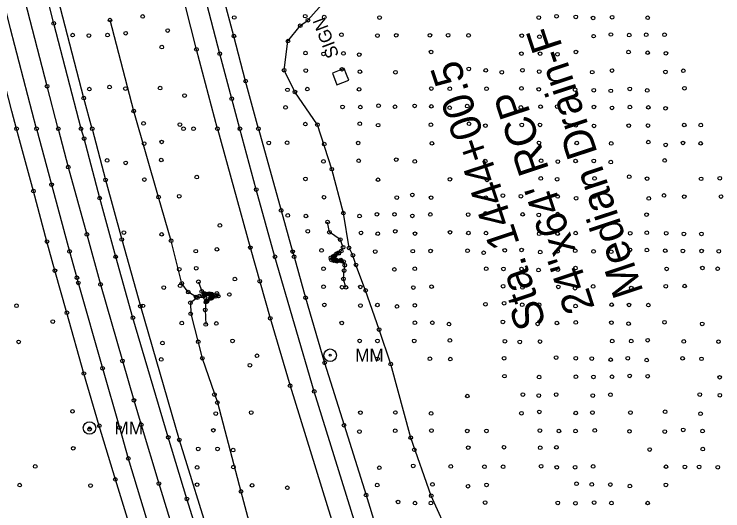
# Model space of a CAD drawing. Extents: x 20503438 to 20508873, y 7964251 to 7984667.
# Drawn here: x 20505603 to 20505990.8, y 7976920.6 to 7977192.3 of the extents above; entities that cross this region are included whole.
import ezdxf

# ---------------------------------------------------------------- set-up
doc = ezdxf.new("R2010")
doc.units = 0
for name, color, linetype in [('SurBreakLine', 7, 'Continuous'), ('SurConcreteSlab', 7, 'Continuous'), ('SurDrainageArrowUp', 7, 'Continuous'), ('SurEdgeRoadPaved', 7, 'Continuous'), ('SurEdgeShoulderPaved', 7, 'Continuous'), ('SurPointsNonDTM', 7, 'Continuous'), ('SurRoadPoints', 7, 'Continuous'), ('SurSurveyPoints', 7, 'Continuous'), ('SurTxtDrainage', 7, 'Continuous')]:
    doc.layers.add(name, color=color, linetype=linetype)

msp = doc.modelspace()

# ---------------------------------------------------------------- linework, layer by layer
at = {"layer": 'SurBreakLine'}
for points in [[(20505627.16, 7977129.6), (20505621, 7977152.86), (20505604.98, 7977215.01)], [(20505714.24, 7977129.6), (20505702.74, 7977172.96), (20505693.54, 7977209.72)], [(20505627.16, 7977129.6), (20505632.6, 7977108.64), (20505642.78, 7977071.79), (20505650.26, 7977044.44), (20505662.27, 7977002.64), (20505668.49, 7976981.08), (20505672.51, 7976967.67), (20505682.17, 7976935.56), (20505689.5, 7976911.63)], [(20505714.24, 7977129.6), (20505732.22, 7977064.58), (20505743.15, 7977025.95), (20505753.96, 7976989.01), (20505776.7, 7976915.92), (20505797.67, 7976849.64), (20505822.91, 7976773.82), (20505835.6, 7976736.75), (20505851.23, 7976692.18), (20505881.78, 7976610.15), (20505895.32, 7976574.73), (20505907.09, 7976544.26), (20505948.4, 7976440.27), (20505966.85, 7976397.06)], [(20505784.52, 7977042.85), (20505783.2, 7977047.48), (20505783.52, 7977052.06), (20505783.93, 7977054.98), (20505783.23, 7977056.95), (20505781.78, 7977057.35), (20505779.53, 7977057.07), (20505777.83, 7977057.46), (20505776.58, 7977057.82), (20505776.33, 7977059.03), (20505777.62, 7977059.8), (20505779.41, 7977061.23), (20505780.72, 7977061.88), (20505781.97, 7977062.67), (20505783.02, 7977064.79), (20505781.42, 7977068.98), (20505775.49, 7977072.98), (20505774.5, 7977078.6)], [(20505703.86, 7977045.89), (20505705.66, 7977040.61), (20505706.75, 7977039.62), (20505707.23, 7977039.41), (20505709.74, 7977039.48), (20505711, 7977039.27), (20505713.91, 7977039.54), (20505714.72, 7977038.09), (20505713.52, 7977038.02), (20505712.02, 7977037.77), (20505710.95, 7977036.83), (20505708.44, 7977035.03), (20505707.88, 7977034.78), (20505707.54, 7977030.55), (20505707.82, 7977022.56)]]:
    msp.add_lwpolyline(points, dxfattribs=at)
at = {"layer": 'SurConcreteSlab'}
for points in [[(20505781.78, 7977057.76), (20505779.2, 7977057.84), (20505778.28, 7977058.25), (20505777.84, 7977058.9), (20505778.13, 7977059.52), (20505780.62, 7977061.42), (20505780.54, 7977061.59), (20505778.63, 7977060.38), (20505777.95, 7977059.64), (20505777.68, 7977058.92), (20505777.91, 7977058.29), (20505778.53, 7977057.75), (20505779.54, 7977057.44), (20505781.82, 7977057.49)], [(20505707.23, 7977039.07), (20505709.48, 7977039.08), (20505710.47, 7977038.91), (20505711.08, 7977038.48), (20505711.05, 7977038), (20505710.84, 7977037.38), (20505710.22, 7977036.7), (20505708.23, 7977035.42), (20505708.39, 7977035.2), (20505710.83, 7977036.95), (20505711.26, 7977037.65), (20505711.23, 7977038.59), (20505710.57, 7977039.1), (20505709.82, 7977039.27), (20505707.52, 7977039.36)]]:
    msp.add_lwpolyline(points, close=True, dxfattribs=at)
at = {"layer": 'SurDrainageArrowUp'}
for points in [[(20505841.57, 7976905.79), (20505831.2, 7976928.87), (20505820.02, 7976960.63), (20505809.08, 7977000.91), (20505802.72, 7977019.77), (20505795.33, 7977041.18), (20505790.04, 7977055.14), (20505788.34, 7977060.44), (20505786.23, 7977064.44), (20505783.14, 7977083.44), (20505776.83, 7977107.5), (20505768.94, 7977131.75), (20505756.6, 7977149.72), (20505750.73, 7977161.63), (20505752.84, 7977177.52), (20505759.52, 7977185.95), (20505763.74, 7977188.93), (20505777.8, 7977204.89)], [(20505707.08, 7977038.35), (20505704.42, 7977038.11), (20505702.5, 7977037.59), (20505698.25, 7977040.29), (20505694.71, 7977045.04), (20505688.86, 7977068.33), (20505681.98, 7977092.2), (20505668.42, 7977139.31), (20505655.45, 7977189.07)], [(20505707.4, 7977037.27), (20505703.17, 7977037.15), (20505699.48, 7977034.43), (20505699.58, 7977028.38), (20505705.95, 7977004.1), (20505714.17, 7976979.83), (20505727.11, 7976931.22), (20505739.64, 7976883.92), (20505750.55, 7976861.92), (20505767.66, 7976808.37), (20505782.7, 7976762.01), (20505813.56, 7976666.44), (20505830.86, 7976618.86), (20505849.64, 7976572.31), (20505867.43, 7976526.9), (20505886.99, 7976479.14), (20505905.22, 7976432.12), (20505914.25, 7976410.54), (20505924.33, 7976390.07)]]:
    msp.add_lwpolyline(points, dxfattribs=at)
at = {"layer": 'SurEdgeRoadPaved'}
for points in [[(20505639.58, 7977129.6), (20505624.63, 7977187.2), (20505615.58, 7977223)], [(20505615.26, 7977129.6), (20505601.04, 7977184.16), (20505592.64, 7977217.57)], [(20505726.55, 7977129.6), (20505722.04, 7977146), (20505715.52, 7977170.61), (20505707.28, 7977202.25)], [(20505667.23, 7976909.32), (20505658.37, 7976937.83), (20505649.59, 7976967.17), (20505641.18, 7976995.74), (20505631.87, 7977028.97), (20505625.28, 7977051.99), (20505620.94, 7977067.88), (20505613.51, 7977095.5), (20505604.33, 7977129.6)], [(20505615.26, 7977129.6), (20505623.45, 7977099.02), (20505633.31, 7977062.48), (20505637.29, 7977048.14), (20505638.09, 7977045.27), (20505651.36, 7976998.65), (20505660.6, 7976966.16), (20505665.45, 7976949.3), (20505675.3, 7976916.84), (20505683.04, 7976892.36), (20505688.19, 7976876.04), (20505701.22, 7976835.1), (20505711.07, 7976804.73), (20505720.51, 7976776.33), (20505734.63, 7976734.41), (20505745.53, 7976702.88), (20505759.33, 7976663.75), (20505771.44, 7976629.94), (20505784.37, 7976595.48), (20505797.7, 7976560.8), (20505811.46, 7976525.6), (20505854.48, 7976420.23), (20505870.79, 7976380.67)], [(20505888.02, 7976400.52), (20505875.61, 7976430.87), (20505858.33, 7976472.87), (20505843.45, 7976509.59), (20505829.21, 7976545.44), (20505815.32, 7976581.21), (20505788.67, 7976653.43), (20505776.13, 7976688.41), (20505761.74, 7976729.52), (20505752.69, 7976755.73), (20505741.62, 7976788.54), (20505730.6, 7976822.27), (20505708.77, 7976891.06), (20505697.53, 7976927.13), (20505687.33, 7976960.85), (20505667.97, 7977026.21), (20505658.55, 7977059.63), (20505649.78, 7977091.67), (20505641.23, 7977124.22), (20505639.58, 7977129.6)], [(20505976.84, 7976403.26), (20505970.11, 7976419.35), (20505955.7, 7976454.64), (20505927.75, 7976523.73), (20505913.86, 7976558.72), (20505899.14, 7976596.95), (20505885.21, 7976633.89), (20505872.02, 7976669.96), (20505859.99, 7976702.29), (20505847.36, 7976737.97), (20505835.6, 7976772.91), (20505824.01, 7976806.63), (20505812.42, 7976841.79), (20505791.67, 7976907.29), (20505767.2, 7976985.93), (20505745.71, 7977059.58), (20505735.47, 7977096.35), (20505726.56, 7977129.6)], [(20505736.67, 7977129.6), (20505749.09, 7977084.93), (20505755.38, 7977062.38), (20505756.16, 7977059.58), (20505762.44, 7977037.2), (20505772.9, 7977001.61), (20505783.49, 7976967.45), (20505795.6, 7976929.21), (20505803.5, 7976903.4), (20505811.19, 7976878.51), (20505817.87, 7976857.03), (20505841.87, 7976784.77), (20505866, 7976715.06), (20505866.99, 7976712.36), (20505882.81, 7976669.26), (20505890.65, 7976647.96), (20505917.09, 7976577.87), (20505938.32, 7976524.67), (20505944.73, 7976508.47), (20505959.58, 7976471.88), (20505973.34, 7976438.98), (20505987.53, 7976403.61)]]:
    msp.add_lwpolyline(points, dxfattribs=at)
at = {"layer": 'SurEdgeShoulderPaved'}
for points in [[(20505645.74, 7977129.6), (20505641.05, 7977146.39), (20505623.31, 7977215.43)], [(20505604.33, 7977129.6), (20505601.72, 7977139.15), (20505583.71, 7977209.07)], [(20505736.67, 7977129.6), (20505729.67, 7977155.64), (20505723.21, 7977180.31), (20505717.62, 7977201.63)], [(20505645.74, 7977129.6), (20505653, 7977101.66), (20505661.85, 7977069.03), (20505672.05, 7977032.49), (20505693.36, 7976959.44), (20505711.05, 7976902.57), (20505727.57, 7976849.37), (20505739.42, 7976813.17), (20505751.74, 7976776.5), (20505761.39, 7976748.39), (20505765.21, 7976737.3), (20505776.34, 7976705.45), (20505803.39, 7976629.54), (20505816.72, 7976594.21), (20505830.99, 7976557.36), (20505845.1, 7976521.55), (20505859.09, 7976486.97), (20505874.74, 7976448.5), (20505889.98, 7976411.65), (20505895.55, 7976397.9)]]:
    msp.add_lwpolyline(points, dxfattribs=at)
at = {"layer": 'SurPointsNonDTM'}
msp.add_circle((20505737.41, 7977046.23), 1, dxfattribs=at)
at = {"layer": 'SurRoadPoints'}
msp.add_lwpolyline([(20505784.83, 7977159.33), (20505784.83, 7977159.33), (20505783.61, 7977162.53), (20505777.21, 7977160.09), (20505779.65, 7977153.69), (20505786.05, 7977156.13), (20505784.83, 7977159.33)], dxfattribs=at)
for centre, radius in [((20505775.89, 7977005.73), 3.43), ((20505775.89, 7977005.73), 0.571), ((20505644.24, 7976965.95), 3.43), ((20505644.24, 7976965.95), 0.571)]:
    msp.add_circle(centre, radius, dxfattribs=at)
at = {"layer": 'SurSurveyPoints'}
for centre in [(20505655.45, 7977189.07), (20505673.32, 7977191.06), (20505723.4, 7977190.45), (20505762.3, 7977191.18), (20505763.74, 7977188.93), (20505772.65, 7977190.67), (20505802.93, 7977190.41), (20505890.09, 7977190.41), (20505899.83, 7977191.11), (20505910.29, 7977190.79), (20505919.77, 7977190.19), (20505930.17, 7977190.59), (20505949.67, 7977190.32), (20505624.63, 7977187.2), (20505759.52, 7977185.95), (20505664.02, 7977181.85), (20505687.01, 7977183.33), (20505782.1, 7977181.03), (20505929.55, 7977181.15), (20505958.9, 7977181.02), (20505634.99, 7977180.82), (20505643.88, 7977180.56), (20505654.09, 7977180.82), (20505723.21, 7977180.31), (20505752.84, 7977177.52), (20505801.8, 7977180.57), (20505812.07, 7977180.7), (20505830.48, 7977180.7), (20505840.42, 7977180.76), (20505851.62, 7977180.67), (20505880.78, 7977180.53), (20505890.46, 7977179.93), (20505920.09, 7977180.24), (20505939.57, 7977180.81), (20505948.86, 7977180.98), (20505683.79, 7977174.24), (20505702.74, 7977172.96), (20505715.52, 7977170.61), (20505762.42, 7977170.95), (20505772.29, 7977170.52), (20505783.16, 7977170.78), (20505791.79, 7977170.14), (20505831.12, 7977171.58), (20505880.6, 7977170.68), (20505890.77, 7977170.69), (20505900.28, 7977170.36), (20505910.41, 7977171.58), (20505939.19, 7977171.55), (20505949.68, 7977171.2), (20505959.66, 7977170.86), (20505750.73, 7977161.63), (20505782.41, 7977162.12), (20505851.79, 7977162.36), (20505762.56, 7977161.44), (20505792.18, 7977160.82), (20505811.66, 7977160.49), (20505861.08, 7977161.54), (20505869.8, 7977160.52), (20505881.14, 7977161.59), (20505890.35, 7977160.88), (20505919.33, 7977160.55), (20505930.16, 7977161.43), (20505959.36, 7977160.72), (20505969.16, 7977161.29), (20505729.67, 7977155.64), (20505621, 7977152.86), (20505644.14, 7977151.26), (20505655.18, 7977152.41), (20505663.9, 7977151.59), (20505682.88, 7977151.82), (20505752.51, 7977150.89), (20505763.4, 7977151.29), (20505791.74, 7977151.16), (20505831.26, 7977151.58), (20505841.37, 7977151.44), (20505861.51, 7977151.48), (20505880.6, 7977151.65), (20505890.1, 7977151.17), (20505909.95, 7977150.91), (20505920.14, 7977150.69), (20505929.47, 7977150.34), (20505939.87, 7977151.4), (20505949.43, 7977150.53), (20505969.77, 7977151.76), (20505641.05, 7977146.39), (20505696.22, 7977147.73), (20505756.6, 7977149.72), (20505722.04, 7977146), (20505668.42, 7977139.31), (20505751.51, 7977141.23), (20505782.71, 7977141.54), (20505792.43, 7977141.45), (20505802.4, 7977142.16), (20505811.38, 7977141.62), (20505822.14, 7977142.11), (20505831.26, 7977141.86), (20505841.31, 7977141.06), (20505850.91, 7977141.99), (20505880.31, 7977141.29), (20505891.07, 7977141.68), (20505900.18, 7977141.72), (20505920.25, 7977141.5), (20505930.16, 7977141.02), (20505939.95, 7977141.46), (20505950.04, 7977141.3), (20505959.43, 7977140.77), (20505673.78, 7977132.52), (20505693.7, 7977131.91), (20505762.33, 7977132.13), (20505768.94, 7977131.75), (20505792.09, 7977132.3), (20505802.13, 7977131.56), (20505831.05, 7977131.81), (20505851.89, 7977132.31), (20505860.86, 7977131.3), (20505880.75, 7977131.74), (20505890.73, 7977131.69), (20505910.35, 7977131.5), (20505920.27, 7977131.14), (20505939.33, 7977131.29), (20505949.84, 7977131.36), (20505969.69, 7977131.65), (20505978.69, 7977131.58), (20505604.33, 7977129.6), (20505604.33, 7977129.6), (20505615.26, 7977129.6), (20505615.26, 7977129.6), (20505627.16, 7977129.6), (20505627.16, 7977129.6), (20505639.58, 7977129.6), (20505639.58, 7977129.6), (20505645.74, 7977129.6), (20505645.74, 7977129.6), (20505695.68, 7977129.6), (20505695.68, 7977129.6), (20505701.16, 7977129.6), (20505701.16, 7977129.6), (20505714.24, 7977129.6), (20505714.24, 7977129.6), (20505726.55, 7977129.6), (20505726.56, 7977129.6), (20505736.67, 7977129.6), (20505736.67, 7977129.6), (20505641.23, 7977124.22), (20505674.08, 7977121.48), (20505683.7, 7977122.37), (20505742.31, 7977121.86), (20505752.37, 7977121.92), (20505772.66, 7977121.2), (20505791.24, 7977121.83), (20505831.6, 7977121.62), (20505890.19, 7977121.87), (20505910.87, 7977121.79), (20505929.72, 7977121.54), (20505950.02, 7977122.31), (20505959.53, 7977120.76), (20505969.01, 7977121.81), (20505978.67, 7977121.61), (20505653.88, 7977112.25), (20505683.46, 7977112.51), (20505772.21, 7977111.74), (20505791.52, 7977112.06), (20505812.05, 7977112.7), (20505822.22, 7977111.7), (20505860.79, 7977111.9), (20505891.34, 7977112.08), (20505900.5, 7977111.68), (20505910.2, 7977111.95), (20505920.18, 7977112.01), (20505929.47, 7977111.35), (20505958.98, 7977112.27), (20505632.6, 7977108.64), (20505664.01, 7977110.91), (20505776.83, 7977107.5), (20505653, 7977101.66), (20505674.23, 7977101.8), (20505702.91, 7977103.14), (20505762.41, 7977102.16), (20505802.09, 7977101.74), (20505841.42, 7977101.94), (20505861.72, 7977101.59), (20505891.18, 7977102.43), (20505900.08, 7977101.97), (20505920.59, 7977102.46), (20505939.58, 7977103.31), (20505949.32, 7977102.32), (20505978.92, 7977102.21), (20505989.14, 7977102.51), (20505623.45, 7977099.02), (20505735.47, 7977096.35), (20505613.51, 7977095.5), (20505681.98, 7977092.2), (20505693.35, 7977092.68), (20505772.54, 7977092.13), (20505812.34, 7977091.97), (20505820.9, 7977093.42), (20505831.17, 7977091.93), (20505861.09, 7977091.85), (20505870.41, 7977093.03), (20505880.32, 7977092.67), (20505900.42, 7977092.57), (20505920.42, 7977092.47), (20505958.6, 7977093.16), (20505969.67, 7977092.46), (20505989.79, 7977092.53), (20505649.78, 7977091.67), (20505910.51, 7977091.62), (20505950.27, 7977091.47), (20505749.09, 7977084.93), (20505752.73, 7977082.2), (20505762.64, 7977081.87), (20505783.14, 7977083.44), (20505792.01, 7977081.83), (20505801.47, 7977082.8), (20505811.12, 7977082.8), (20505820.89, 7977081.93), (20505830.72, 7977082.74), (20505851.43, 7977082.65), (20505860.93, 7977083.34), (20505881.26, 7977082.78), (20505890.07, 7977082.46), (20505900.43, 7977082.91), (20505949.08, 7977082.62), (20505715.55, 7977076.73), (20505774.5, 7977078.6), (20505663.06, 7977072.8), (20505763.64, 7977073.57), (20505775.49, 7977072.98), (20505792.8, 7977072.65), (20505811.51, 7977073.51), (20505841.48, 7977072.97), (20505851.58, 7977072.57), (20505861.2, 7977072.52), (20505910.27, 7977072.56), (20505940.15, 7977072.43), (20505949.16, 7977072.72), (20505959.83, 7977072.47), (20505642.78, 7977071.79), (20505661.85, 7977069.03), (20505683.72, 7977071.84), (20505781.42, 7977068.98), (20505801.95, 7977072.22), (20505822.36, 7977072.23), (20505890.33, 7977072.17), (20505900.41, 7977072.2), (20505969.49, 7977072.09), (20505979.1, 7977072.08), (20505620.94, 7977067.88), (20505688.86, 7977068.33), (20505783.02, 7977064.79), (20505633.31, 7977062.48), (20505702.37, 7977062.65), (20505713.9, 7977063.65), (20505732.22, 7977064.58), (20505755.38, 7977062.38), (20505771.18, 7977063.02), (20505779.41, 7977061.23), (20505780.54, 7977061.59), (20505780.62, 7977061.42), (20505780.72, 7977061.88), (20505781.97, 7977062.67), (20505786.23, 7977064.44), (20505800.6, 7977062.44), (20505821.09, 7977062.65), (20505830.84, 7977062.75), (20505851.12, 7977062.84), (20505859.9, 7977061.74), (20505871.43, 7977063.12), (20505880.64, 7977063.3), (20505890.89, 7977062.12), (20505900.34, 7977062.64), (20505910.05, 7977062.87), (20505920.06, 7977062.48), (20505929.72, 7977062.35), (20505940, 7977063.33), (20505949.27, 7977063.24), (20505959.28, 7977062.91), (20505968.95, 7977062.82), (20505979.14, 7977062.74), (20505988.59, 7977062.64), (20505658.55, 7977059.63), (20505745.71, 7977059.58), (20505756.16, 7977059.58), (20505776.33, 7977059.03), (20505776.58, 7977057.82), (20505777.62, 7977059.8), (20505777.68, 7977058.92), (20505777.83, 7977057.46), (20505777.84, 7977058.9), (20505777.91, 7977058.29), (20505777.95, 7977059.64), (20505778.13, 7977059.52), (20505778.28, 7977058.25), (20505778.53, 7977057.75), (20505778.63, 7977060.38), (20505779.2, 7977057.84), (20505779.53, 7977057.07), (20505779.54, 7977057.44), (20505781.78, 7977057.76), (20505781.78, 7977057.35), (20505781.82, 7977057.49), (20505783.23, 7977056.95), (20505788.34, 7977060.44), (20505702.6, 7977053.32), (20505772.29, 7977053.04), (20505783.93, 7977054.98), (20505790.04, 7977055.14), (20505822.23, 7977053.05), (20505910.15, 7977053.41), (20505979.62, 7977053.46), (20505625.28, 7977051.99), (20505693.3, 7977052.74), (20505783.52, 7977052.06), (20505811.05, 7977052.68), (20505861.33, 7977052.99), (20505870.71, 7977052.93), (20505880.63, 7977052.88), (20505889.95, 7977052.28), (20505900.55, 7977052.59), (20505960.04, 7977052.93), (20505987.96, 7977053.04), (20505637.29, 7977048.14), (20505703.86, 7977045.89), (20505723.78, 7977047.38), (20505783.2, 7977047.48), (20505638.09, 7977045.27), (20505650.26, 7977044.44), (20505684.87, 7977042.75), (20505693.79, 7977043.73), (20505694.71, 7977045.04), (20505772.3, 7977043.16), (20505782.39, 7977042.92), (20505784.52, 7977042.85), (20505792.41, 7977043.07), (20505821.41, 7977042.73), (20505831.41, 7977043.22), (20505870.57, 7977043.45), (20505881.19, 7977042.82), (20505900.76, 7977043.11), (20505909.88, 7977042.38), (20505919.82, 7977043.39), (20505940.68, 7977042.52), (20505959.57, 7977043.44), (20505969.91, 7977043.59), (20505698.25, 7977040.29), (20505702.5, 7977037.59), (20505704.42, 7977038.11), (20505705.66, 7977040.61), (20505706.75, 7977039.62), (20505707.08, 7977038.35), (20505707.23, 7977039.41), (20505707.23, 7977039.07), (20505707.52, 7977039.36), (20505709.48, 7977039.08), (20505709.74, 7977039.48), (20505709.82, 7977039.27), (20505710.47, 7977038.91), (20505710.57, 7977039.1), (20505711, 7977039.27), (20505711.05, 7977038), (20505711.08, 7977038.48), (20505711.23, 7977038.59), (20505711.26, 7977037.65), (20505712.02, 7977037.77), (20505713.52, 7977038.02), (20505713.91, 7977039.54), (20505714.72, 7977038.09), (20505720.75, 7977038.95), (20505795.33, 7977041.18), (20505699.48, 7977034.43), (20505703.17, 7977037.15), (20505707.4, 7977037.27), (20505707.88, 7977034.78), (20505708.23, 7977035.42), (20505708.39, 7977035.2), (20505708.44, 7977035.03), (20505710.22, 7977036.7), (20505710.83, 7977036.95), (20505710.84, 7977037.38), (20505710.95, 7977036.83), (20505762.44, 7977037.2), (20505871.11, 7977034.19), (20505604.27, 7977032.77), (20505672.05, 7977032.49), (20505673.42, 7977032.75), (20505707.54, 7977030.55), (20505772.73, 7977033.26), (20505792.5, 7977032.91), (20505801.81, 7977033.2), (20505812.48, 7977032.39), (20505822.25, 7977033.04), (20505860.86, 7977033.64), (20505881, 7977033.3), (20505890.24, 7977033.36), (20505910.19, 7977032.61), (20505929.97, 7977033.37), (20505939.44, 7977033.22), (20505950.03, 7977033.14), (20505631.87, 7977028.97), (20505667.97, 7977026.21), (20505699.58, 7977028.38), (20505743.15, 7977025.95), (20505624.14, 7977024.13), (20505694.73, 7977023.31), (20505707.82, 7977022.56), (20505713.62, 7977023.14), (20505782.29, 7977023.37), (20505822.26, 7977023.46), (20505831.83, 7977023.49), (20505840.95, 7977022.75), (20505870.42, 7977023.99), (20505889.45, 7977022.85), (20505899.97, 7977023.34), (20505910.31, 7977023.66), (20505929.81, 7977023.56), (20505939.2, 7977022.98), (20505958.87, 7977023.77), (20505979.53, 7977022.87), (20505802.72, 7977019.77), (20505605.45, 7977013.03), (20505684.16, 7977012.36), (20505703.7, 7977013.07), (20505722.5, 7977013.55), (20505792.04, 7977013.59), (20505801.81, 7977013.54), (20505821.92, 7977013.59), (20505841.45, 7977013.85), (20505871.56, 7977013.38), (20505879.68, 7977013.05), (20505890.73, 7977013.21), (20505930.26, 7977013.47), (20505940.66, 7977013.43), (20505949.67, 7977013.93), (20505969.39, 7977013.25), (20505988.42, 7977013.14), (20505662.27, 7977002.64), (20505683.49, 7977003.41), (20505705.95, 7977004.1), (20505735.86, 7977005.42), (20505801.83, 7977003.76), (20505830.47, 7977003.81), (20505841.66, 7977003.61), (20505871.08, 7977004.09), (20505899.55, 7977004.43), (20505910.3, 7977004.08), (20505919.05, 7977003.93), (20505929.4, 7977003.3), (20505938.8, 7977004.08), (20505949.13, 7977003.05), (20505968.79, 7977004.03), (20505979.12, 7977003.76), (20505731.99, 7977000.28), (20505772.9, 7977001.61), (20505809.08, 7977000.91), (20505641.18, 7976995.74), (20505651.36, 7976998.65), (20505871.3, 7976994.28), (20505890.25, 7976993.75), (20505910.36, 7976993.96), (20505919.97, 7976993.88), (20505930.15, 7976993.94), (20505939.81, 7976994.46), (20505949.68, 7976994.22), (20505989.04, 7976993.66), (20505753.96, 7976989.01), (20505712.56, 7976984.22), (20505767.2, 7976985.93), (20505850.96, 7976983.43), (20505881.39, 7976984.22), (20505890.1, 7976983.66), (20505899.59, 7976984.21), (20505919.63, 7976983.68), (20505929.27, 7976984.12), (20505978.16, 7976984.19), (20505989.15, 7976983.83), (20505668.49, 7976981.08), (20505714.17, 7976979.83), (20505634.91, 7976975.03), (20505713.29, 7976973.8), (20505732.73, 7976974.36), (20505792.51, 7976974.33), (20505811.59, 7976974.41), (20505831.18, 7976973.91), (20505880.58, 7976974), (20505890.36, 7976974.76), (20505910.34, 7976974.12), (20505919.46, 7976974.37), (20505940.24, 7976974.35), (20505959.19, 7976974.8), (20505978.61, 7976973.7), (20505644.25, 7976965.22), (20505649.59, 7976967.17), (20505660.6, 7976966.16), (20505672.51, 7976967.67), (20505712, 7976964.66), (20505783.49, 7976967.45), (20505791.9, 7976963.97), (20505811.54, 7976964.45), (20505831.33, 7976964.56), (20505850.91, 7976964.3), (20505861.41, 7976964.32), (20505890.7, 7976964.51), (20505901.07, 7976964.29), (20505910.23, 7976964.21), (20505920.72, 7976964.57), (20505939.72, 7976964.13), (20505959.05, 7976963.96), (20505969.14, 7976964.89), (20505979.72, 7976964.24), (20505687.33, 7976960.85), (20505820.02, 7976960.63), (20505693.36, 7976959.44), (20505635.32, 7976954.82), (20505703.71, 7976954.5), (20505714.27, 7976954.48), (20505722.81, 7976953.82), (20505821.98, 7976954.04), (20505851.44, 7976955.18), (20505871.02, 7976955.39), (20505890.87, 7976955.1), (20505899.75, 7976955.35), (20505950.76, 7976954.16), (20505979.79, 7976954.4), (20505665.45, 7976949.3), (20505614.49, 7976944.88), (20505722.98, 7976944.56), (20505821.37, 7976945.22), (20505841.88, 7976944.94), (20505860.32, 7976944.7), (20505870.53, 7976944.74), (20505891.32, 7976945.04), (20505919.79, 7976944.94), (20505959.69, 7976944.78), (20505970.06, 7976944.66), (20505977.78, 7976944.64), (20505988.02, 7976944.46), (20505703.08, 7976944.36), (20505802.8, 7976944.16), (20505899.92, 7976944.44), (20505909.96, 7976944.45), (20505658.37, 7976937.83), (20505606.01, 7976934.7), (20505644.78, 7976934.46), (20505682.17, 7976935.56), (20505703.09, 7976934.95), (20505733.2, 7976934.57), (20505752.48, 7976933.27), (20505801.65, 7976934.71), (20505831.87, 7976935.07), (20505851.35, 7976934.08), (20505861.48, 7976934.8), (20505910.72, 7976935.45), (20505919.1, 7976935.07), (20505929.24, 7976935.02), (20505939.96, 7976934.18), (20505959.61, 7976934.79), (20505727.11, 7976931.22), (20505795.6, 7976929.21), (20505697.53, 7976927.13), (20505813.08, 7976925.46), (20505831.2, 7976928.87), (20505860.72, 7976925.14), (20505920.33, 7976925.15), (20505822.35, 7976924.86), (20505831.05, 7976924.84), (20505900.48, 7976924.99), (20505910.13, 7976924.77), (20505929.86, 7976924.87), (20505949.65, 7976924.91)]:
    msp.add_circle(centre, 1, dxfattribs=at)

# ---------------------------------------------------------------- texts
at = {"layer": 'SurRoadPoints'}
for s, rotation, p in [('SIGN', 110.9142, (20505780.9, 7977169.83)), ('MM', 360, (20505789.6, 7977002.24)), ('MM', 360, (20505657.95, 7976962.46))]:
    msp.add_text(s, height=6.995, rotation=rotation, dxfattribs=at).set_placement(p)
at = {"layer": 'SurTxtDrainage'}
for s, p in [('Median Drain-F', (20505947.48, 7977040.53)), ('Sta. 1444+00.5', (20505894.31, 7977022.94)), ('24"x64\' RCP', (20505920.89, 7977031.73))]:
    msp.add_text(s, height=16.8, rotation=108.2983, dxfattribs=at).set_placement(p)

doc.saveas('drawing.dxf')
